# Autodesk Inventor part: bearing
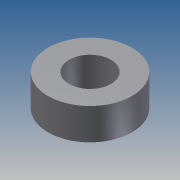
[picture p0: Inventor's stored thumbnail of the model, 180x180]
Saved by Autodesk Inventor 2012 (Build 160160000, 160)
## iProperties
Created: 2012-04
Part Number: bearing
Material: Default
Document SubType Name: Modeling
Designer: win32
Density: 1 g/cm^3
Author: win32
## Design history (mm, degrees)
sketch "Sketch1"
  geometry: C1 r 10 at (0, 0); C2 r 20 at (0, 0); 1 further point
  constraints: 2 centre point, 2 coincident
  dimensions: "d0" = 20 diameter of C1; "d1" = 40 diameter of C2
extrude "Extrusion1" new body sketch "Sketch1" distance "d2" = 15; taper "d3" = 0 deg
body "Solid1"
